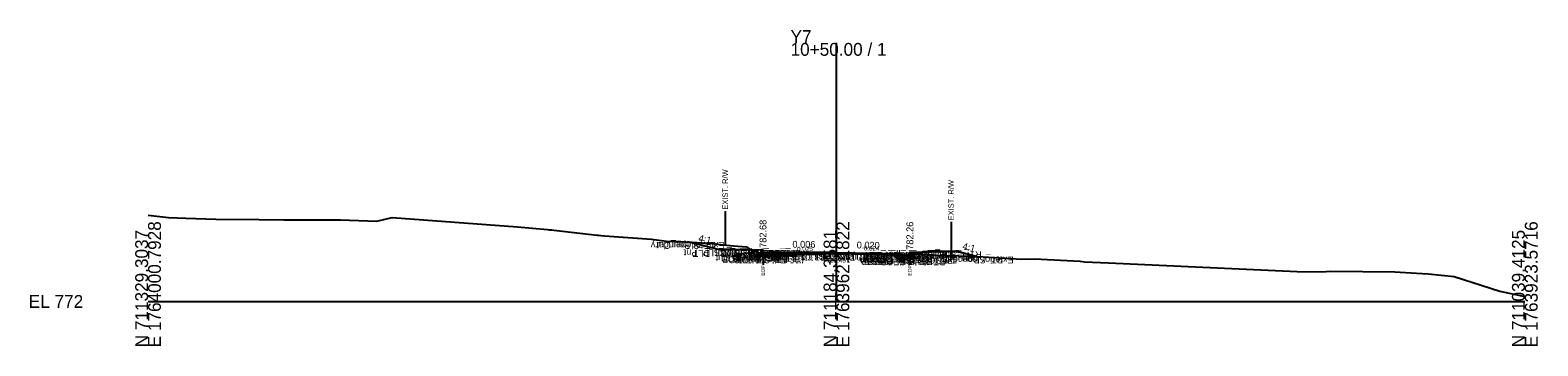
# Model space of a CAD drawing. Extents: x -26 to 2903, y -10 to 1056.
# Drawn here: x -25.7 to 302.8, y 490.3 to 559.2 of the extents above; entities that cross this region are included whole.
import ezdxf

# ---------------------------------------------------------------- set-up
doc = ezdxf.new("R2010")
doc.units = 0
for name, color, linetype in [('Default', 7, 'Continuous'), ('Exist CMT Pavement', 7, 'Continuous'), ('Exist Cross Section Cell', 7, 'Continuous'), ('Exist XS Center Line Elevation Label', 7, 'Continuous'), ('Exist XS Ground Line', 7, 'Continuous'), ('Old_Level_10', 7, 'Continuous'), ('Prop CMT Conc Surface', 7, 'Continuous'), ('Prop CMT Concrete Structures', 7, 'Continuous'), ('Prop CMT Pvmt Course 1', 7, 'Continuous'), ('Prop CMT Pvmt Course 1 CG', 7, 'Continuous'), ('Prop CMT Pvmt Course 2', 7, 'Continuous'), ('Prop CMT Pvmt Course 3', 7, 'Continuous'), ('Prop CMT Pvmt Surface', 7, 'Continuous'), ('Prop CMT Slope Grass', 7, 'Continuous'), ('Prop CMT Subgrade Earthwork', 7, 'Continuous'), ('Prop XS Earthwork Shape', 7, 'Continuous'), ('Prop XS Hydro Elevations', 7, 'Continuous'), ('Prop XS SE Text', 7, 'Continuous'), ('Prop XS Side Slope Text', 7, 'Continuous'), ('Prop XS Wedging', 7, 'Continuous'), ('Scratch_Level_1', 7, 'Continuous'), ('Scratch_Level_7', 7, 'Continuous')]:
    doc.layers.add(name, color=color, linetype=linetype)

msp = doc.modelspace()

# ---------------------------------------------------------------- linework, layer by layer
at = {"layer": 'Exist CMT Pavement'}
msp.add_lwpolyline([(137.01, 510.12), (138.1, 510.16), (150, 510.45), (150.93, 510.47), (155.12, 510.35), (162.99, 510.14)], dxfattribs=at)
at = {"layer": 'Exist Cross Section Cell'}
for p, q in [((150, 500), (150, 556.38)), ((0, 500), (150, 500)), ((150, 500), (300, 500))]:
    msp.add_line(p, q, dxfattribs=at)
at = {"layer": 'Exist XS Ground Line'}
msp.add_lwpolyline([(0, 518.79), (4.45, 518.31), (8.26, 518.18), (14.8, 517.91), (24.19, 517.84), (29.55, 517.8), (39.96, 517.79), (41.91, 517.79), (49.83, 517.5), (53.2, 518.3), (80.49, 516.24), (87.06, 515.66), (87.49, 515.65), (87.97, 515.63), (88.4, 515.53), (97.83, 514.44), (98.15, 514.42), (98.64, 514.4), (99.44, 514.34), (109.69, 513.55), (112.97, 513.18), (116.12, 513.08), (120.51, 512.76), (122.83, 512.62), (123.64, 512.58), (125.36, 512.36), (127.57, 512.15), (130.38, 511.88), (131.25, 511.35), (133.48, 510.45), (134.01, 510.03), (138.1, 510.16), (150, 510.45), (150.93, 510.47), (155.12, 510.35), (166, 510.07), (166.55, 510.45), (171.45, 510.08), (179.29, 509.87), (179.93, 509.82), (180.28, 509.81), (180.75, 509.79), (190.42, 509.19), (193.18, 509.27), (203.09, 508.76), (204.04, 508.66), (209.29, 508.4), (250.38, 506.54), (255.78, 506.44), (257.67, 506.59), (271.71, 506.44), (276.37, 506.18), (278.91, 506.05), (284.64, 505.44), (294.55, 502.26), (300, 501.08)], dxfattribs=at)
at = {"layer": 'Old_Level_10'}
for p, q in [((125.75, 519.72), (125.75, 512.32)), ((174.98, 517.39), (174.98, 509.98)), ((134.01, 510.03), (134.01, 507.98)), ((166, 510.07), (166, 508.02))]:
    msp.add_line(p, q, dxfattribs=at)
at = {"layer": 'Prop CMT Conc Surface'}
for points in [[(134, 510.68), (134, 511.18), (133.5, 511.18)], [(136, 510.75), (134, 510.68)], [(164, 510.38), (166, 510.26)], [(166, 510.26), (166, 510.76), (166.5, 510.76)]]:
    msp.add_lwpolyline(points, dxfattribs=at)
at = {"layer": 'Prop CMT Concrete Structures'}
for points in [[(136, 510.75), (134, 510.68), (134, 511.18), (133.5, 511.18)], [(133.5, 511.18), (133.5, 510.18), (136, 510.16)], [(136, 510.16), (136, 510.75)], [(164, 510.38), (166, 510.26), (166, 510.76), (166.5, 510.76)], [(166.5, 510.76), (166.5, 509.75), (164, 509.8)], [(164, 509.8), (164, 510.38)]]:
    msp.add_lwpolyline(points, dxfattribs=at)
at = {"layer": 'Prop CMT Pvmt Course 1'}
for p, q in [((148.82, 510.42), (142.03, 510.46)), ((142.03, 510.46), (142.24, 510.26)), ((142.24, 510.26), (148.82, 510.42)), ((162.99, 510.15), (162.04, 510.17)), ((162.04, 510.17), (162.99, 510.14)), ((162.99, 510.14), (162.99, 510.15))]:
    msp.add_line(p, q, dxfattribs=at)
for points in [[(150, 510.66), (136, 510.75)], [(136, 510.75), (136, 510.5)], [(136, 510.5), (136.01, 510.5)], [(136.01, 510.5), (150, 510.41)], [(136.01, 510.5), (136.01, 510.5)], [(150, 510.41), (150, 510.66)], [(150, 510.66), (164, 510.38)], [(150, 510.41), (150, 510.41), (150, 510.41)], [(164, 510.13), (150, 510.41)], [(164, 510.13), (163.99, 510.13)], [(163.99, 510.13), (163.99, 510.13)], [(164, 510.38), (164, 510.13)]]:
    msp.add_lwpolyline(points, dxfattribs=at)
at = {"layer": 'Prop CMT Pvmt Course 1 CG'}
for p, q in [((136, 510.16), (137.01, 510.16)), ((164, 509.8), (162.99, 509.82))]:
    msp.add_line(p, q, dxfattribs=at)
for points in [[(136, 510.16), (133, 510.18), (132.67, 509.85)], [(132.67, 509.85), (136, 509.83)], [(136, 509.83), (136, 510.16)], [(164, 509.46), (164, 509.8)], [(164, 509.8), (167, 509.74), (167.34, 509.4)], [(167.34, 509.4), (164, 509.46)]]:
    msp.add_lwpolyline(points, dxfattribs=at)
at = {"layer": 'Prop CMT Pvmt Course 2'}
for points in [[(136.01, 510.5), (136, 510.5)], [(136, 510.5), (136, 510.16)], [(136, 510.16), (136.01, 510.16)], [(137.01, 510.16), (137.01, 510.49)], [(162.99, 509.82), (162.99, 510.15)], [(163.99, 510.13), (164, 510.13)], [(164, 509.8), (163.99, 509.8)], [(164, 510.13), (164, 509.8)]]:
    msp.add_lwpolyline(points, dxfattribs=at)
at = {"layer": 'Prop CMT Pvmt Course 3'}
for points in [[(136, 510.16), (136, 509.83)], [(136, 509.83), (136.01, 509.83)], [(137.01, 509.83), (137.01, 510.16)], [(162.99, 509.49), (162.99, 509.82)], [(164, 509.46), (163.99, 509.46)], [(164, 509.8), (164, 509.46)], [(164, 509.46), (164, 509.46)]]:
    msp.add_lwpolyline(points, dxfattribs=at)
at = {"layer": 'Prop CMT Pvmt Surface'}
for points in [[(150, 510.66), (136, 510.75)], [(150, 510.66), (164, 510.38)]]:
    msp.add_lwpolyline(points, dxfattribs=at)
at = {"layer": 'Prop CMT Slope Grass'}
for points in [[(133.5, 511.18), (124, 511.37), (117.6, 512.97)], [(166.5, 510.76), (176, 510.95), (180.61, 509.8)]]:
    msp.add_lwpolyline(points, dxfattribs=at)
at = {"layer": 'Prop CMT Subgrade Earthwork'}
for p, q in [((137.01, 509.82), (137.01, 510.12)), ((162.99, 509.48), (162.99, 510.14)), ((162.99, 509.48), (164, 509.46))]:
    msp.add_line(p, q, dxfattribs=at)
for points in [[(136, 509.83), (132.67, 509.85), (131.3, 511.22)], [(137.01, 509.82), (136, 509.83)], [(164, 509.46), (167.34, 509.4), (168.75, 510.81)]]:
    msp.add_lwpolyline(points, dxfattribs=at)
at = {"layer": 'Prop XS Earthwork Shape'}
for points in [[(131.56, 511.22), (131.3, 511.22), (124, 511.37), (117.6, 512.97), (120.51, 512.76), (122.83, 512.62), (123.64, 512.58), (125.36, 512.36), (127.57, 512.15), (130.38, 511.88), (131.25, 511.35)], [(131.56, 511.22), (131.3, 511.22), (132.67, 509.85), (136, 509.83), (137.01, 509.82), (137.01, 510.12), (134.01, 510.03), (133.48, 510.45)], [(162.99, 510.14), (166, 510.07), (166.55, 510.45), (168.26, 510.32), (167.34, 509.4), (164, 509.46), (162.99, 509.48)], [(168.26, 510.32), (171.45, 510.08), (179.29, 509.87), (179.93, 509.82), (180.28, 509.81), (180.61, 509.8), (176, 510.95), (168.75, 510.81)]]:
    msp.add_lwpolyline(points, close=True, dxfattribs=at)
at = {"layer": 'Prop XS Wedging'}
for p, q in [((137.01, 510.49), (137.01, 510.16)), ((137.01, 510.16), (137.01, 510.12)), ((142.24, 510.26), (142.03, 510.46))]:
    msp.add_line(p, q, dxfattribs=at)
for points in [[(142.03, 510.46), (142.03, 510.46), (138.1, 510.49), (137.01, 510.49)], [(137.01, 510.49), (137.01, 510.49)], [(137.01, 510.12), (138.1, 510.16), (142.24, 510.26)]]:
    msp.add_lwpolyline(points, dxfattribs=at)
at = {"layer": 'Scratch_Level_1'}
for p, q in [((135.87, 510.02), (150, 510.45)), ((150, 510.45), (166, 510.07))]:
    msp.add_line(p, q, dxfattribs=at)

# ---------------------------------------------------------------- texts
at = {"layer": 'Default'}
msp.add_text('-', height=0.0001, dxfattribs=at).set_placement((0, 500))
at = {"layer": 'Exist Cross Section Cell'}
for s, p in [('Y7', (140, 556.38)), ('10+50.00 / 1', (140, 553.58)), ('EL 772', (-26, 498.6))]:
    msp.add_text(s, height=2.8, dxfattribs=at).set_placement(p)
for s, p in [('E 1764000.7928', (2.8, 490)), ('E 1763962.1822', (152.8, 490)), ('E 1763923.5716', (302.8, 490)), ('N 711329.3037', (0, 490)), ('N 711184.3581', (150, 490)), ('N 711039.4125', (300, 490))]:
    msp.add_text(s, height=2.8, rotation=90, dxfattribs=at).set_placement(p)
at = {"layer": 'Exist XS Center Line Elevation Label'}
msp.add_text('782.45', height=1, dxfattribs=at).set_placement((147.87, 508.45))
at = {"layer": 'Old_Level_10'}
for s, height, p in [('EXIST. R/W', 1.181, (126.34, 520.02)), ('EXIST. R/W', 1.181, (175.57, 517.69)), ('EOP', 0.787, (134.4, 505.58)), ('EOP', 0.787, (166.39, 505.62))]:
    msp.add_text(s, height=height, rotation=90, dxfattribs=at).set_placement(p)
at = {"layer": 'Prop XS Hydro Elevations'}
for s, p in [('782.68', (134.75, 511.68)), ('782.26', (166.75, 511.26))]:
    msp.add_text(s, height=1.5, rotation=90, dxfattribs=at).set_placement(p)
at = {"layer": 'Prop XS SE Text'}
for s, rotation, p in [('0.006', 359.6419, (140.4, 511.72)), ('0.020', 358.8542, (154.4, 511.57))]:
    msp.add_text(s, height=1.5, rotation=rotation, dxfattribs=at).set_placement(p)
at = {"layer": 'Prop XS Side Slope Text'}
for p in [(119.83, 513.19), (177.33, 511.39)]:
    msp.add_text('4:1', height=1.5, rotation=345.9638, dxfattribs=at).set_placement(p)
at = {"layer": 'Scratch_Level_1'}
for s, rotation, p in [('0.025', 1.4596, (141.42, 510.9)), ('0.024', 358.6376, (155.94, 511.13))]:
    msp.add_text(s, height=1, rotation=rotation, dxfattribs=at).set_placement(p)
at = {"layer": 'Scratch_Level_7'}
for s, p in [('Exterior Boundary', (125.61, 512.97)), ('LT_Slope_Cut', (123.6, 512.97)), ('LT_CSLP_Pnt', (129.55, 511.37)), ('LT_Sub_Trench_Out_DLT', (142.32, 511.22)), ('LT_CG1_Shelf_Out', (141.27, 510.18)), ('LT_CG_Top_BOC', (141.14, 511.18)), ('LT_CG_Bot_BOC', (140.93, 510.18)), ('LT_CG_Top_Face', (141.62, 511.18)), ('LT_Sub_OEOP', (139.02, 509.85)), ('LT_CG_Top_Gut', (141.22, 510.68)), ('LT_PV1_OEEOP', (142.74, 510.5)), ('LT_PV2_OEEOP', (142.92, 510.5)), ('LT_PV3_OEEOP', (142.92, 510.16)), ('LT_Sub_OEEOP', (142.88, 509.83)), ('LT_PV1_OEOT', (142.2, 510.75)), ('LT_PV2_OEOT', (142.38, 510.5)), ('LT_PV3_OEOT', (142.38, 510.16)), ('LT_Sub_OEOT', (142.35, 509.83)), ('LT_CG_Bot_IE', (142.12, 510.16)), ('RT_PV1_IEEOP', (156.25, 510.41)), ('RT_PV2_IEEOP', (156.43, 510.41)), ('LT_PV1_IEEOP', (156.16, 510.41)), ('LT_PV2_IEEOP', (156.34, 510.41)), ('PV1_PGL', (153.8, 510.66)), ('PV2_PGL', (153.98, 510.41)), ('RT_PV1_OEEOP', (170.82, 510.13)), ('RT_PV2_OEEOP', (171, 510.13)), ('RT_PV3_OEEOP', (171, 509.8)), ('RT_Sub_OEEOP', (170.96, 509.46)), ('RT_Sub_Trench_Out_DLT', (179.86, 510.81)), ('RT_PV1_OEOT', (170.29, 510.38)), ('RT_PV2_OEOT', (170.47, 510.13)), ('RT_PV3_OEOT', (170.47, 509.8)), ('RT_Sub_OEOT', (170.44, 509.46)), ('RT_CG_Bot_IE', (170.21, 509.8)), ('RT_CG_Top_Face', (173.71, 510.76)), ('RT_CG1_Shelf_Out', (175.36, 509.74)), ('RT_CG_Top_BOC', (174.23, 510.76)), ('RT_CG_Top_Gut', (173.31, 510.26)), ('RT_CG_Bot_BOC', (174.02, 509.75)), ('RT_Sub_OEOP', (173.78, 509.4)), ('RT_CSLP_Pnt', (181.64, 510.95)), ('Exterior Boundary', (188.62, 509.8)), ('RT_Slope_Fill', (186.34, 509.8))]:
    msp.add_text(s, height=1.5, rotation=180, dxfattribs=at).set_placement(p)

doc.saveas('drawing.dxf')
